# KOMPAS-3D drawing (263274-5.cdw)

Views: Вид 1
Referenced files in /: n6, h9, h7
Referenced files in I:\контрольыне\: Чертеж.cdw
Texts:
  Редуктор двухступенчатый  цилендрический
  Loner-XP
  DreamLair
  Текст на чертеже
  Размерные надписи
  Шероховатость
  Линия-выноска #1
  Линия-выноска #2
  Линия-выноска #3
  Отклонения формы и база
  Заголовок таблицы
  Ячейка таблицы
  Стрелка вида
  Обозначение изменения
  Фигурная скобка
  Номер узла
  Марка координационной оси
  VRCB
  Выносная надпись
  Обозначение узла
  Марка/позиционное обозначение с линией-выноской
  Марка/позиционное обозначение на линии
  Марка/позиционное обозначение без линии-выноски
  Normal
  Symbol
  Symbol type A
  JS9
  JS7
  Технические характеристика:
  1. Мощность передаваемая редуктором 5 кВт
  2. КПД редуктора 0,98
  3. Частота вращения выходного вала 231,2 об/мин
  4. Степень точность: Быстроходная ступень 9В
  5. Крутящий момент  на выходном валу 209,56Нм
  Стандартные изделия
  Шпонка 6x6x14 ГОСТ 23360-78
  Шпонка 10x8x22 ГОСТ 23360-78
  Шпонка 14x9x36 ГОСТ 23360-78
  Отверстие Ф5,5x10
  Болт М6-8gx18.109.30ХГСА ГОСТ 15589-70
  Шпонка 14x12x36 ГОСТ 10748-79
  Гайка  М5-6H.04 ГОСТ 5927-70
  Шайба C 5.31 ГОСТ 10450-78
  Винт В.М2,5-6gx5.109.30ХГСА ГОСТ 17473-80
  Отверстие Ф5,3
  Болт М6-8gx60.109.30ХГСА ГОСТ 15589-70
  Шайба C 6.31 ГОСТ 10450-78
  Гайка  М6-6H.04 ГОСТ 15524-70
  Отверстие Ф2,9/Ф3,1x90°
  Болт М3-6gx26.43 ОСТ 92-0722-72
  Шайба C 3.31 ГОСТ 10450-78
  Гайка 2М3-6H.04 ГОСТ 5916-70
  Отверстие Ф5,5x18
  Гайка М10-6H.04 ГОСТ 5927-70
  Гайка
  ГОСТ
  Шайба C  6 ГОСТ 10450-78
  Шайба
  .Ти9
  АМг5 ГОСТ 4784-97
  Винт В.М 2,5-6g x 5.109.30ХГСА ГОСТ 17473-80
  Винт обычный
  Винт
  .30ХГСА
  Сталь 30ХГСА ГОСТ 4543-71
  Шпонка 6 x 6 x 14 ГОСТ 23360-78
  Шпонка
  Шпонка 10 x 8 x 22 ГОСТ 23360-78
  Шпонка 14 x 9 x 36 ГОСТ 23360-78
  Подшипник305 ГОСТ 8338-75
  Подшипник
  Подшипник306 ГОСТ 8338-75
  Подшипник309 ГОСТ 8338-75
  Шпонка 14 x 9 x 36 ГОСТ 10748-79
  Болт М10-8g x 120 109.30ХГСА ГОСТ 15589-70
  Болт
  Шайба C  6.31 ГОСТ 10450-78
  Болт М6-6g x 52 ОСТ 92 -722-72
  ОСТ 92
  Шайба C  10 ГОСТ 10450-78
  Гайка  М6-6H.04 ГОСТ 5916-70
  Манжета
  Манжета 1.1-25 x52-1 / 4 ГОСТ 8752-79
  Болт М-6g x 18 109.30ХГСА ГОСТ 15589-70
  Корпус редуктора
  Крышка редуктора
  Вал - шестерня
  вал - шестерня
  вал
  Пробка сливная М16х15
  Щуп М14х1,5
  Отдушина М10х1,5
  Крышка смотрового отверстия
  Колесо
  Крышка
  Втулка
  Прокладка
  Редуктор двухступенчатый
  цилендрический
  Месечко А.В.
  ВНУ им. Даля
  гр. МЗ - 06в
Dimensions and other numbers on the sheet: 701.48.00.000. ВО; 7; 18; 25; 136; 178; 32; 30; 23; 45; 38; 45,6; 418; 220; 146,06; 6; 10; 8; 46; 50; 9; 14; 62; 72; 100; 125; 71; 1; 12; 2; 5; 13; 3; 4; 11; 15; 16; 17; 19; 20; 21; 22; 24; 26; 27; 28; 29; 31; 33; 34; 35; 36; 37; 92; 150; 260; 348; -6H; 70; 0,002573; 78; 0,00011139010113; -6g; 80; 0,000261; 0,003576; 0,01245; 0,03263; 305; 75; 306; 0,331; 309; 0,828; 79; 0,04304; -8g; 0,01564; 0,00027195426779136; 2,68214194248E-5; 0,000218; 52; 701.48.00.001; 701.48.00.002; 701.48.00.003; 701.48.00.004; 1:1; 701.13.00.000. ВО-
